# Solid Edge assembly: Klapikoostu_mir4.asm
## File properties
Author: Türk
Template: Iso Assembly.asm
Last saved by: Türk
Revision: 3
Application: Solid Edge
Username: Türk
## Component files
Klapi vedru_mir.par
Klapp.par
Klapipuks.par
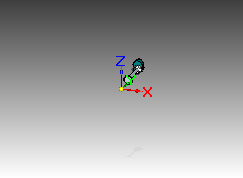
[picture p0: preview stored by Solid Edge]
